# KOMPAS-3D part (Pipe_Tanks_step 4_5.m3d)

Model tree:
1. X Axis
2. Y Axis
3. Z Axis  (labels: Valve Dy 150; Pipe Dn 150)
     Òîëùèíà ñòåíêè 1 = 1

Referenced files in C:\Documents and Settings\kashirsky\Мои документы\Camtasia Studio\Pipelines3D\Tanks\: Tanks_step 4.a3d
Referenced files in C:\Program Files\ASCON\KOMPAS-3D V10\Libs\Piping\LOAD\: Piping_C_Pipe_150_1000.m3d
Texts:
  Pipe Dn 150
  Steel ASTM A295
  Three Point Plane
  Plane at Angle
  Line and Point Plane
  Axis through Two Vertices
  Axis of Feature
  Axis of Conical Surface
  Axis through Edge
  Trim by Surface
  Trim by Sketch
  Feature with No History
  Intersection Axis of Two Planes
  Two Line Plane
  Line and Face Plane
  Bend by line
  Hole in sheet body
  Cut in sheet body
  Point in CM
  Linear Dimension from Line to Point
  Surface Finish Symbol
  Geometric Tolerance Symbol
  Leader #1
  Leader #2
  Leader #3
  Shape Deviations and Datum
  Node point number
  Mark of coordination axis
  Node point designation
  Mark/Reference designation with leader
  Mark/reference designation on line
  Mark/Reference designation without leader
  Valve Dy 150
  Plane of section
